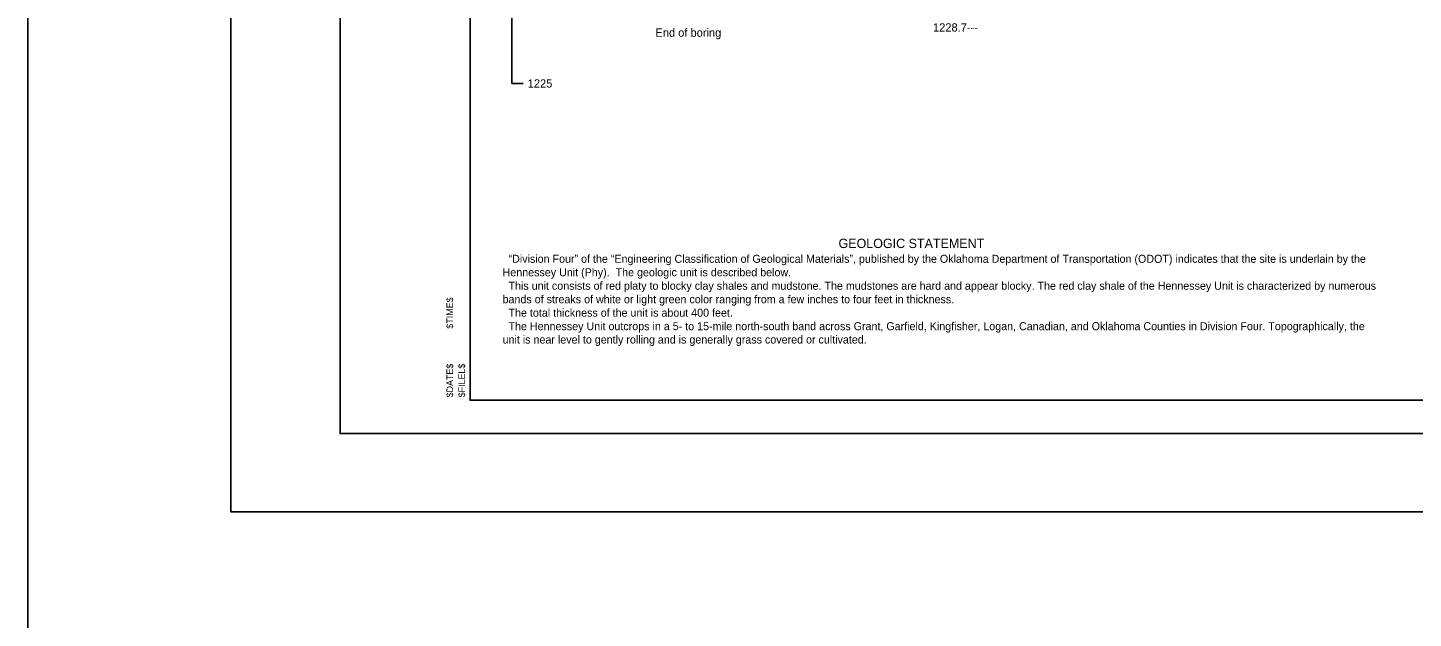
# Model space of a CAD drawing. Extents: x 2150161.5 to 2150203.1, y 143779.5 to 143868.5.
# Drawn here: x 2150161.53 to 2150182.3, y 143808.09 to 143816.95 of the extents above; entities that cross this region are included whole.
import ezdxf

# ---------------------------------------------------------------- set-up
doc = ezdxf.new("R2010")
doc.units = 0
for name, color, linetype in [('Default', 7, 'Continuous'), ('S', 7, 'Continuous'), ('SHT_Plot_Shape_Full', 7, 'Continuous'), ('SHT_Plot_Shape_Half', 7, 'Continuous'), ('SHT_Plot_Stamp', 7, 'Continuous'), ('SHT_Sheet_Border', 7, 'Continuous'), ('Text', 7, 'Continuous')]:
    doc.layers.add(name, color=color, linetype=linetype)

# ---------------------------------------------------------------- blocks, each defined once
blk = doc.blocks.new('Stamp_Plot_Stamp')
at = {"layer": 'SHT_Plot_Stamp'}
for s, p in [('$TIME$', (1.695, 1.572)), ('$DATE$', (1.695, 0.542)), ('$FILEL$', (1.873, 0.542))]:
    blk.add_text(s, height=0.1, rotation=90, dxfattribs=at).set_placement(p)

msp = doc.modelspace()

# ---------------------------------------------------------------- linework, layer by layer
at = {"layer": 'Default'}
msp.add_line((2150168.788, 143816.11), (2150168.788, 143829.746), dxfattribs=at)
msp.add_lwpolyline([(2150168.788, 143816.11), (2150168.955, 143816.11)], dxfattribs=at)
at = {"layer": 'S'}
msp.add_lwpolyline([(2150161.53, 143868.477), (2150203.071, 143868.477), (2150203.071, 143779.536), (2150161.53, 143779.536)], close=True, dxfattribs=at)
at = {"layer": 'SHT_Plot_Shape_Full'}
msp.add_lwpolyline([(2150164.575, 143833.688), (2150200.575, 143833.688), (2150200.575, 143809.688), (2150164.575, 143809.688)], close=True, dxfattribs=at)
at = {"layer": 'SHT_Plot_Shape_Half'}
msp.add_lwpolyline([(2150166.212, 143832.863), (2150200.212, 143832.863), (2150200.212, 143810.863), (2150166.212, 143810.863)], close=True, dxfattribs=at)
at = {"layer": 'SHT_Sheet_Border'}
msp.add_lwpolyline([(2150199.662, 143811.363), (2150168.162, 143811.363), (2150168.162, 143832.363), (2150199.662, 143832.363)], close=True, dxfattribs=at)

# ---------------------------------------------------------------- block references
at = {"layer": 'SHT_Plot_Stamp'}
msp.add_blockref('Stamp_Plot_Stamp', (2150166.212, 143810.863), dxfattribs=at)

# ---------------------------------------------------------------- texts
at = {"layer": 'Default'}
for s, p in [('1228.7---', (2150175.101, 143816.888)), ('End of boring', (2150170.94, 143816.81)), ('1225', (2150169.025, 143816.048))]:
    msp.add_text(s, height=0.124, dxfattribs=at).set_placement(p)
at = {"layer": 'Text'}
for s, height, p in [('GEOLOGIC STATEMENT', 0.14, (2150173.684, 143813.643)), ('  “Division Four” of the “Engineering Classification of Geological Materials”, published by the Oklahoma Department of Transportation (ODOT) indicates that the site is underlain by the ', 0.12, (2150168.648, 143813.422)), ('Hennessey Unit (Phy).  The geologic unit is described below. ', 0.12, (2150168.648, 143813.22)), ('  This unit consists of red platy to blocky clay shales and mudstone. The mudstones are hard and appear blocky. The red clay shale of the Hennessey Unit is characterized by numerous ', 0.12, (2150168.648, 143813.018)), ('bands of streaks of white or light green color ranging from a few inches to four feet in thickness. ', 0.12, (2150168.648, 143812.816)), ('  The total thickness of the unit is about 400 feet.', 0.12, (2150168.648, 143812.614)), ('  The Hennessey Unit outcrops in a 5- to 15-mile north-south band across Grant, Garfield, Kingfisher, Logan, Canadian, and Oklahoma Counties in Division Four. Topographically, the ', 0.12, (2150168.648, 143812.412)), ('unit is near level to gently rolling and is generally grass covered or cultivated.', 0.12, (2150168.648, 143812.212))]:
    msp.add_text(s, height=height, dxfattribs=at).set_placement(p)

doc.saveas('drawing.dxf')
